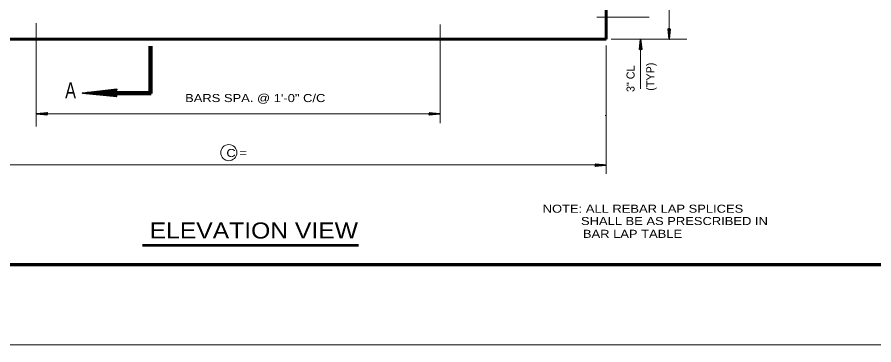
# Model space of a CAD drawing. Extents: x 14.14 to 17.34, y -1.61 to 0.38.
# Drawn here: x 14.587 to 15.473, y -1.605 to -1.266 of the extents above; entities that cross this region are included whole.
import ezdxf

# ---------------------------------------------------------------- set-up
doc = ezdxf.new("R2010")
doc.units = 0
doc.header["$LTSCALE"] = 0.0033
doc.layers.add('1', color=7, linetype='Continuous', lineweight=40)

msp = doc.modelspace()

# ---------------------------------------------------------------- linework, layer by layer
at = {"layer": '1', "lineweight": 13}
for p, q in [((15.261083, -0.873583), (15.261083, -1.288417)), ((15.18625, -1.26575), (15.24025, -1.26575)), ((14.60675, -1.271833), (14.60675, -1.378833)), ((15.024417, -1.27325), (15.024417, -1.375417)), ((15.195917, -1.288417), (15.195917, -1.28875)), ((15.200917, -1.288417), (15.27925, -1.288417)), ((15.195917, -1.294917), (15.195917, -1.376667)), ((15.2315, -1.339667), (15.2315, -1.298417)), ((14.60675, -1.365833), (15.024417, -1.365833)), ((15.19475, -1.36725), (15.195333, -1.36725)), ((15.195917, -1.375083), (15.195917, -1.42775)), ((14.447083, -1.4185), (14.830083, -1.4185)), ((14.830083, -1.4185), (15.1955, -1.4185)), ((17.339333, -1.60475), (14.142583, -1.60475))]:
    msp.add_line(p, q, dxfattribs=at)
at = {"layer": '1', "lineweight": 35}
for p, q in [((15.26, -1.278083), (15.260833, -1.285417)), ((15.260167, -1.278083), (15.260917, -1.285417)), ((15.26025, -1.278083), (15.261083, -1.285417)), ((15.260417, -1.278), (15.261167, -1.285333)), ((15.261917, -1.278083), (15.260917, -1.285917)), ((15.261083, -1.277833), (15.261083, -1.288417)), ((15.261917, -1.278083), (15.261083, -1.285917)), ((15.262083, -1.278083), (15.261167, -1.285917)), ((15.262083, -1.278083), (15.261167, -1.285917)), ((15.262, -1.278083), (15.261167, -1.285917)), ((15.2305, -1.298833), (15.231417, -1.291)), ((15.2305, -1.298833), (15.231417, -1.291)), ((15.230583, -1.298833), (15.231417, -1.291)), ((15.230667, -1.298833), (15.2315, -1.291)), ((15.230667, -1.298833), (15.231667, -1.291)), ((15.232167, -1.298917), (15.231417, -1.291583)), ((15.2315, -1.299083), (15.2315, -1.2885)), ((15.232333, -1.298833), (15.2315, -1.2915)), ((15.232417, -1.298833), (15.231667, -1.2915)), ((15.232583, -1.298833), (15.23175, -1.2915)), ((14.690083, -1.34425), (14.654417, -1.34425)), ((14.689333, -1.347), (14.66275, -1.343667)), ((14.689333, -1.347), (14.66275, -1.34425)), ((14.689333, -1.347667), (14.66275, -1.344417)), ((14.689333, -1.347667), (14.66275, -1.344417)), ((14.689333, -1.34725), (14.66275, -1.344417)), ((14.689333, -1.3405), (14.664583, -1.34325)), ((14.689333, -1.341), (14.664583, -1.343667)), ((14.689333, -1.341417), (14.664583, -1.34425)), ((14.689583, -1.342), (14.664667, -1.344417)), ((14.618, -1.36575), (14.607417, -1.36575)), ((14.61775, -1.366583), (14.609917, -1.365583)), ((14.61775, -1.366583), (14.609917, -1.36575)), ((14.61775, -1.36675), (14.609917, -1.365833)), ((14.61775, -1.36675), (14.609917, -1.365833)), ((14.61775, -1.366667), (14.609917, -1.365833)), ((14.61775, -1.364667), (14.610417, -1.3655)), ((14.61775, -1.364833), (14.610417, -1.365583)), ((14.61775, -1.364917), (14.610417, -1.36575)), ((14.617833, -1.365083), (14.6105, -1.365833)), ((15.013, -1.365583), (15.023583, -1.365583)), ((15.013167, -1.36625), (15.0205, -1.3655)), ((15.01325, -1.364583), (15.021083, -1.3655)), ((15.01325, -1.364583), (15.021083, -1.3655)), ((15.01325, -1.364667), (15.021083, -1.3655)), ((15.01325, -1.36475), (15.021083, -1.365583)), ((15.01325, -1.36475), (15.021083, -1.36575)), ((15.01325, -1.366417), (15.020583, -1.365583)), ((15.01325, -1.3665), (15.020583, -1.36575)), ((15.01325, -1.366667), (15.020583, -1.365833)), ((15.1845, -1.418667), (15.195083, -1.418667)), ((15.184667, -1.419333), (15.192, -1.418583)), ((15.18475, -1.417667), (15.192583, -1.418583)), ((15.18475, -1.417667), (15.192583, -1.418583)), ((15.18475, -1.41775), (15.192583, -1.418583)), ((15.18475, -1.417833), (15.192583, -1.418667)), ((15.18475, -1.417833), (15.192583, -1.418833)), ((15.18475, -1.4195), (15.192083, -1.418667)), ((15.18475, -1.419583), (15.192083, -1.418833)), ((15.18475, -1.41975), (15.192083, -1.418917))]:
    msp.add_line(p, q, dxfattribs=at)
at = {"layer": '1', "lineweight": 60}
for p, q in [((14.791917, -1.288417), (14.445917, -1.288417)), ((15.195917, -1.288417), (14.7725, -1.288417))]:
    msp.add_line(p, q, dxfattribs=at)
at = {"layer": '1', "lineweight": 90}
for p, q in [((14.724833, -1.2955), (14.724833, -1.313333)), ((14.724833, -1.302833), (14.724833, -1.3445)), ((14.7255, -1.344333), (14.683833, -1.344333))]:
    msp.add_line(p, q, dxfattribs=at)
at = {"layer": '1', "lineweight": 53}
msp.add_line((14.7165, -1.501417), (14.93975, -1.501417), dxfattribs=at)
at = {"layer": '1', "lineweight": 70}
msp.add_line((14.309333, -1.521417), (17.256, -1.521417), dxfattribs=at)
at = {"layer": '1', "lineweight": 60}
msp.add_lwpolyline([(15.112583, -0.87175), (15.112583, -1.205083), (15.195917, -1.205083), (15.195917, -1.288417)], dxfattribs=at)
at = {"layer": '1'}
msp.add_lwpolyline([(14.309333, -1.521417), (16.671, -1.521417), (16.671, -1.196333), (17.256, -1.196333)], dxfattribs=at)
at = {"layer": '1', "lineweight": 35}
for points in [[(15.262167, -1.277833), (15.261083, -1.288417), (15.259917, -1.277833), (15.261083, -1.278417)], [(15.261167, -1.278583), (15.26125, -1.28325), (15.261167, -1.28325), (15.261167, -1.282333), (15.26125, -1.278583), (15.261333, -1.281583), (15.261417, -1.278417), (15.2615, -1.280667), (15.261583, -1.278417), (15.261333, -1.281917), (15.261167, -1.286583), (15.260917, -1.285667), (15.260917, -1.286917), (15.260917, -1.278583), (15.26075, -1.281), (15.26075, -1.278417), (15.261167, -1.28375), (15.2605, -1.278417)], [(15.230417, -1.299083), (15.2315, -1.2885), (15.232667, -1.299083), (15.2315, -1.2985)], [(15.231417, -1.298333), (15.231333, -1.293667), (15.231417, -1.293667), (15.231417, -1.294583), (15.231333, -1.298333), (15.23125, -1.295333), (15.231167, -1.2985), (15.231083, -1.29625), (15.231, -1.2985), (15.23125, -1.295), (15.231417, -1.290333), (15.231667, -1.29125), (15.231667, -1.29), (15.231667, -1.298333), (15.231833, -1.295917), (15.231833, -1.2985), (15.231417, -1.293167), (15.232083, -1.2985)], [(14.690083, -1.34775), (14.654417, -1.34425), (14.690083, -1.34025), (14.688167, -1.34425)], [(14.687667, -1.344417), (14.671833, -1.34475), (14.671833, -1.344417), (14.674833, -1.344417), (14.687667, -1.34475), (14.677417, -1.345), (14.688167, -1.345417), (14.680417, -1.3455), (14.688167, -1.345917), (14.676333, -1.345), (14.6605, -1.344417), (14.663583, -1.343667), (14.659417, -1.343667), (14.687667, -1.343667), (14.679333, -1.343167), (14.688167, -1.343167), (14.670167, -1.344417), (14.688167, -1.342167)], [(14.618, -1.366833), (14.607417, -1.36575), (14.618, -1.364583), (14.617417, -1.36575)], [(14.61725, -1.365833), (14.612583, -1.365917), (14.612583, -1.365833), (14.6135, -1.365833), (14.61725, -1.365917), (14.61425, -1.366), (14.617417, -1.366083), (14.615167, -1.366167), (14.617417, -1.36625), (14.613917, -1.366), (14.60925, -1.365833), (14.610167, -1.365583), (14.608917, -1.365583), (14.61725, -1.365583), (14.614833, -1.365417), (14.617417, -1.365417), (14.612083, -1.365833), (14.617417, -1.365167)], [(15.013, -1.3645), (15.023583, -1.365583), (15.013, -1.36675), (15.013583, -1.365583)], [(15.01375, -1.3655), (15.018417, -1.365417), (15.018417, -1.3655), (15.0175, -1.3655), (15.01375, -1.365417), (15.01675, -1.365333), (15.013583, -1.36525), (15.015833, -1.365167), (15.013583, -1.365083), (15.017083, -1.365333), (15.02175, -1.3655), (15.020833, -1.36575), (15.022083, -1.36575), (15.01375, -1.36575), (15.016167, -1.365917), (15.013583, -1.365917), (15.018917, -1.3655), (15.013583, -1.366167)], [(15.1845, -1.417583), (15.195083, -1.418667), (15.1845, -1.419833), (15.185083, -1.418667)], [(15.18525, -1.418583), (15.189917, -1.4185), (15.189917, -1.418583), (15.189, -1.418583), (15.18525, -1.4185), (15.18825, -1.418417), (15.185083, -1.418333), (15.187333, -1.41825), (15.185083, -1.418167), (15.188583, -1.418417), (15.19325, -1.418583), (15.192333, -1.418833), (15.193583, -1.418833), (15.18525, -1.418833), (15.187667, -1.419), (15.185083, -1.419), (15.190417, -1.418583), (15.185083, -1.41925)]]:
    msp.add_lwpolyline(points, close=True, dxfattribs=at)
for points in [[(15.261167, -1.278583), (15.261917, -1.278167), (15.261667, -1.278417), (15.261333, -1.278583), (15.261417, -1.278833), (15.26175, -1.278667), (15.261, -1.2785), (15.2605, -1.278333), (15.260083, -1.278083)], [(15.231417, -1.298333), (15.230667, -1.29875), (15.230917, -1.2985), (15.23125, -1.298333), (15.231167, -1.298083), (15.230833, -1.29825), (15.231583, -1.298417), (15.232083, -1.298583), (15.2325, -1.298833)], [(14.687667, -1.344417), (14.688917, -1.347), (14.688167, -1.346167), (14.687667, -1.345), (14.686667, -1.345417), (14.687333, -1.3465), (14.687833, -1.343917), (14.688417, -1.342167), (14.689333, -1.340917)], [(14.61725, -1.365833), (14.617667, -1.366583), (14.617417, -1.366333), (14.61725, -1.366), (14.617, -1.366083), (14.617167, -1.366417), (14.617333, -1.365667), (14.6175, -1.365167), (14.61775, -1.36475)], [(15.01375, -1.3655), (15.013333, -1.36475), (15.013583, -1.365), (15.01375, -1.365333), (15.014, -1.36525), (15.013833, -1.364917), (15.013667, -1.365667), (15.0135, -1.366167), (15.01325, -1.366583)], [(15.18525, -1.418583), (15.184833, -1.417833), (15.185083, -1.418083), (15.18525, -1.418417), (15.1855, -1.418333), (15.185333, -1.418), (15.185167, -1.41875), (15.185, -1.41925), (15.18475, -1.419667)]]:
    msp.add_lwpolyline(points, dxfattribs=at)
at = {"layer": '1', "lineweight": 13}
msp.add_circle((14.80575, -1.405833), 0.008333, dxfattribs=at)

# ---------------------------------------------------------------- texts
at = {"layer": '1'}
for s, p in [('3" CL', (15.22525, -1.343083)), ('(TYP)', (15.245667, -1.34175))]:
    msp.add_text(s, height=0.008334, rotation=90, dxfattribs=at).set_placement(p)
for s, height, width, p in [('A', 0.01667, 0.75, (14.636583, -1.349583)), ('BARS SPA. @ 1\'-0" C/C', 0.008334, 1.2, (14.760583, -1.3535)), ('C =      ', 0.008334, 1.2, (14.80325, -1.410333)), ('NOTE: ALL REBAR LAP SPLICES', 0.008334, 1.2, (15.13025, -1.468)), ('ELEVATION VIEW', 0.01658, 1.15, (14.723917, -1.494667)), ('SHALL BE AS PRESCRIBED IN', 0.008334, 1.2, (15.169833, -1.48075)), ('BAR LAP TABLE', 0.008334, 1.2, (15.171833, -1.494))]:
    msp.add_text(s, height=height, dxfattribs=dict(at, width=width)).set_placement(p)

doc.saveas('drawing.dxf')
